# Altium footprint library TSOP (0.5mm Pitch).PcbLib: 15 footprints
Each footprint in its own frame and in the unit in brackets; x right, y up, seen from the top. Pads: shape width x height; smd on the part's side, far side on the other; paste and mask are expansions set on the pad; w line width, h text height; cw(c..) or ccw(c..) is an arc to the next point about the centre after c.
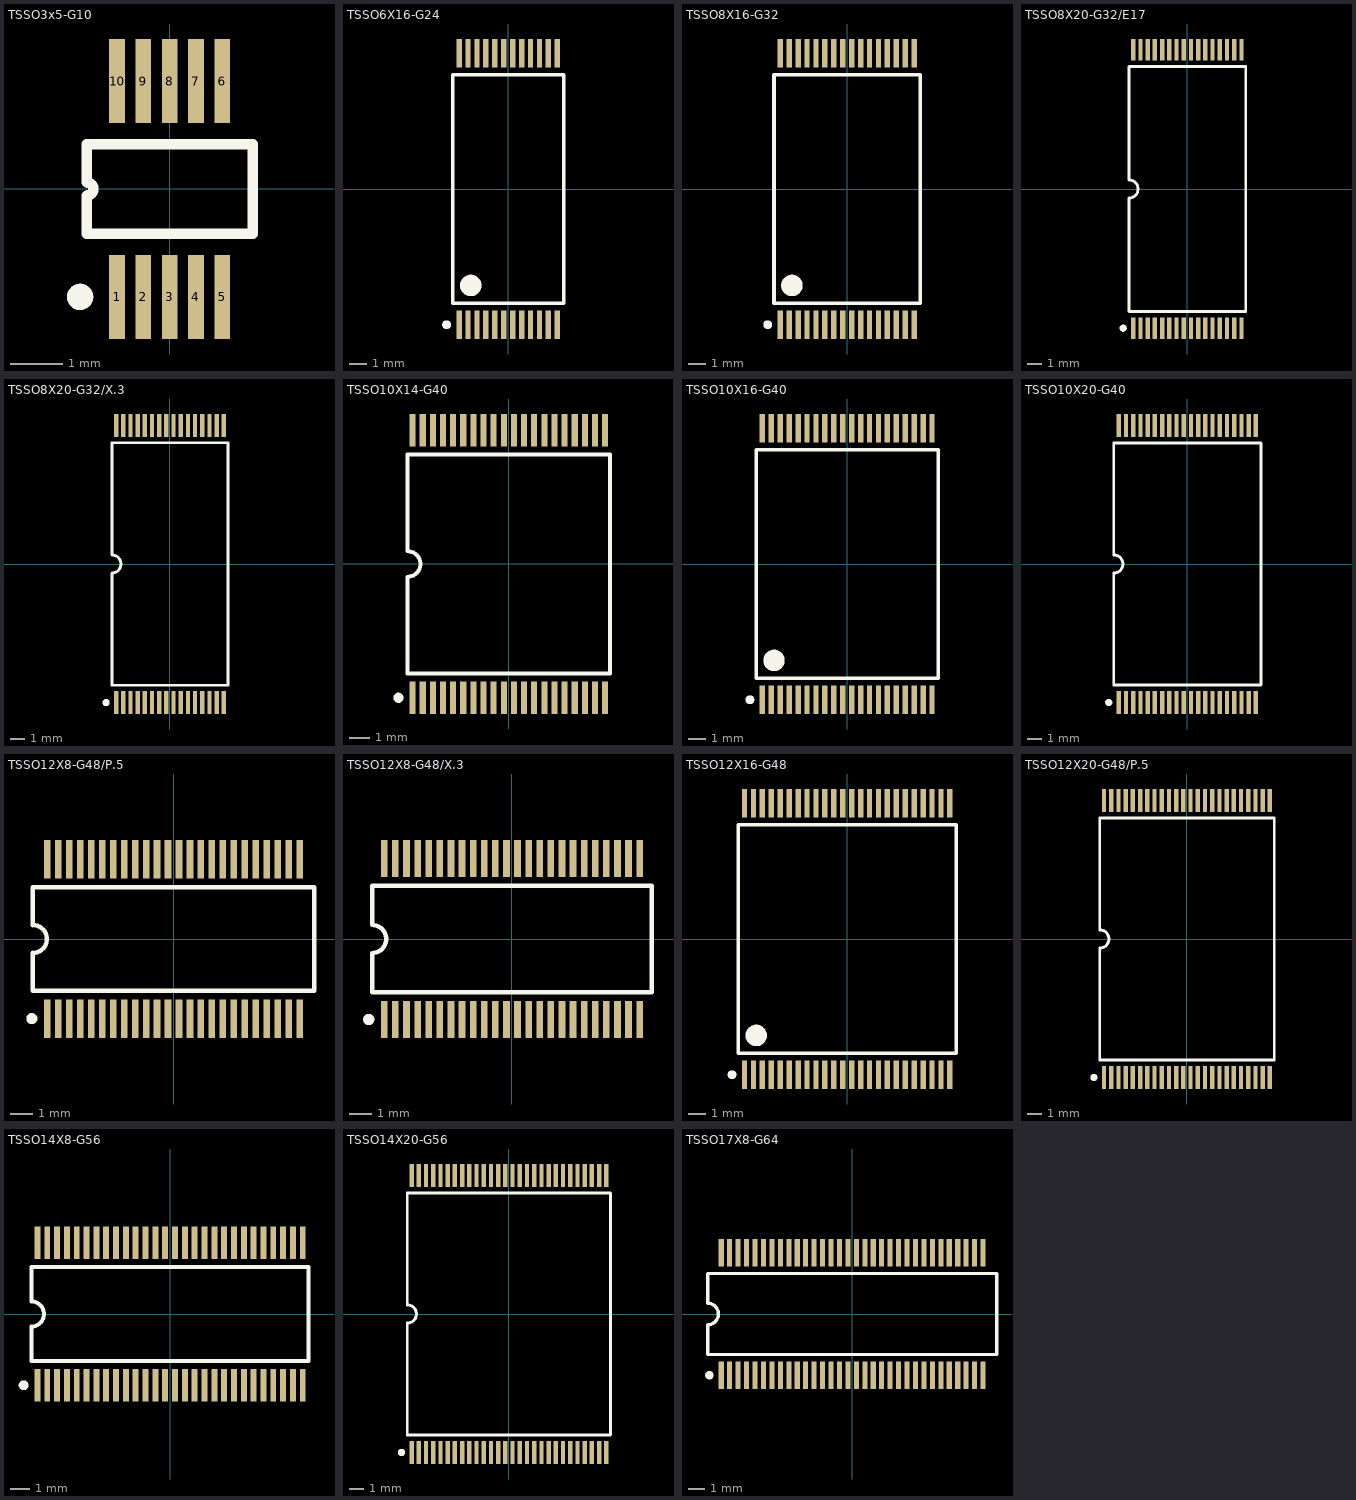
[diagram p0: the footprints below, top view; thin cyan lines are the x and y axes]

## TSSO3x5-G10 [mm]
pads (10):
  rect 0.3x1.6 smd: 1(-1,-2.05) 2(-0.5,-2.05) 3(0,-2.05) 4(0.5,-2.05) 5(1,-2.05) 6(1,2.05) 7(0.5,2.05) 8(0,2.05) 9(-0.5,2.05) 10(-1,2.05)
Top Overlay:
  circle w0.25: c-1.7,-2.05 r0.125
  lines w0.2: -1.575,-0.85 1.575,-0.85 1.575,0.85 -1.575,0.85 -1.575,0.125 cw(c-1.575,0) -1.575,-0.125 -1.575,-0.85

## TSSO6X16-G24 [mm]
pads (24):
  rect 0.3x1.6 smd: 1(-2.75,-7.6) 2(-2.25,-7.6) 3(-1.75,-7.6) 4(-1.25,-7.6) 5(-0.75,-7.6) 6(-0.25,-7.6) 7(0.25,-7.6) 8(0.75,-7.6) 9(1.25,-7.6) 10(1.75,-7.6) 11(2.25,-7.6) 12(2.75,-7.6) 13(2.75,7.6) 14(2.25,7.6) 15(1.75,7.6) 16(1.25,7.6) 17(0.75,7.6) 18(0.25,7.6) 19(-0.25,7.6) 20(-0.75,7.6) 21(-1.25,7.6) 22(-1.75,7.6) 23(-2.25,7.6) 24(-2.75,7.6)
Top Overlay:
  circle w0.6: c-2.1,-5.4 r0.3
  circle w0.25: c-3.45,-7.6 r0.125
  lines w0.2: -3.1,-6.4 3.1,-6.4 3.1,6.4 -3.1,6.4 -3.1,-0.635 -3.1,-6.4

## TSSO8X16-G32 [mm]
pads (32):
  rect 0.3x1.6 smd: 1(-3.75,-7.6) 2(-3.25,-7.6) 3(-2.75,-7.6) 4(-2.25,-7.6) 5(-1.75,-7.6) 6(-1.25,-7.6) 7(-0.75,-7.6) 8(-0.25,-7.6) 9(0.25,-7.6) 10(0.75,-7.6) 11(1.25,-7.6) 12(1.75,-7.6) 13(2.25,-7.6) 14(2.75,-7.6) 15(3.25,-7.6) 16(3.75,-7.6) 17(3.75,7.6) 18(3.25,7.6) 19(2.75,7.6) 20(2.25,7.6) 21(1.75,7.6) 22(1.25,7.6) 23(0.75,7.6) 24(0.25,7.6) 25(-0.25,7.6) 26(-0.75,7.6) 27(-1.25,7.6) 28(-1.75,7.6) 29(-2.25,7.6) 30(-2.75,7.6) 31(-3.25,7.6) 32(-3.75,7.6)
Top Overlay:
  circle w0.6: c-3.1,-5.4 r0.3
  circle w0.25: c-4.45,-7.6 r0.125
  lines w0.2: -4.1,-6.4 4.1,-6.4 4.1,6.4 -4.1,6.4 -4.1,-0.635 -4.1,-6.4

## TSSO8X20-G32/E17 [mm]
pads (32):
  rect 0.3x1.5 smd: 1(-3.75,-9.65) 2(-3.25,-9.65) 3(-2.75,-9.65) 4(-2.25,-9.65) 5(-1.75,-9.65) 6(-1.25,-9.65) 7(-0.75,-9.65) 8(-0.25,-9.65) 9(0.25,-9.65) 10(0.75,-9.65) 11(1.25,-9.65) 12(1.75,-9.65) 13(2.25,-9.65) 14(2.75,-9.65) 15(3.25,-9.65) 16(3.75,-9.65) 17(3.75,9.65) 18(3.25,9.65) 19(2.75,9.65) 20(2.25,9.65) 21(1.75,9.65) 22(1.25,9.65) 23(0.75,9.65) 24(0.25,9.65) 25(-0.25,9.65) 26(-0.75,9.65) 27(-1.25,9.65) 28(-1.75,9.65) 29(-2.25,9.65) 30(-2.75,9.65) 31(-3.25,9.65) 32(-3.75,9.65)
Top Overlay:
  circle w0.25: c-4.45,-9.65 r0.125
  lines w0.2: -4.05,-8.5 4.05,-8.5 4.05,8.5 -4.05,8.5 -4.05,0.635 cw(c-4.05,0) -4.05,-0.635 -4.05,-8.5

## TSSO8X20-G32/X.3 [mm]
pads (32):
  rect 0.3x1.6 smd: 1(-3.75,-9.65) 2(-3.25,-9.65) 3(-2.75,-9.65) 4(-2.25,-9.65) 5(-1.75,-9.65) 6(-1.25,-9.65) 7(-0.75,-9.65) 8(-0.25,-9.65) 9(0.25,-9.65) 10(0.75,-9.65) 11(1.25,-9.65) 12(1.75,-9.65) 13(2.25,-9.65) 14(2.75,-9.65) 15(3.25,-9.65) 16(3.75,-9.65) 17(3.75,9.65) 18(3.25,9.65) 19(2.75,9.65) 20(2.25,9.65) 21(1.75,9.65) 22(1.25,9.65) 23(0.75,9.65) 24(0.25,9.65) 25(-0.25,9.65) 26(-0.75,9.65) 27(-1.25,9.65) 28(-1.75,9.65) 29(-2.25,9.65) 30(-2.75,9.65) 31(-3.25,9.65) 32(-3.75,9.65)
Top Overlay:
  circle w0.25: c-4.45,-9.65 r0.125
  lines w0.2: -4.05,-8.45 -4.05,-0.635 ccw(c-4.05,0) -4.05,0.635 -4.05,8.45 4.05,8.45 4.05,-8.45 -4.05,-8.45

## TSSO10X14-G40 [mm]
pads (40):
  rect 0.3x1.6 smd: 1(-4.75,-6.6) 2(-4.25,-6.6) 3(-3.75,-6.6) 4(-3.25,-6.6) 5(-2.75,-6.6) 6(-2.25,-6.6) 7(-1.75,-6.6) 8(-1.25,-6.6) 9(-0.75,-6.6) 10(-0.25,-6.6) 11(0.25,-6.6) 12(0.75,-6.6) 13(1.25,-6.6) 14(1.75,-6.6) 15(2.25,-6.6) 16(2.75,-6.6) 17(3.25,-6.6) 18(3.75,-6.6) 19(4.25,-6.6) 20(4.75,-6.6) 21(4.75,6.6) 22(4.25,6.6) 23(3.75,6.6) 24(3.25,6.6) 25(2.75,6.6) 26(2.25,6.6) 27(1.75,6.6) 28(1.25,6.6) 29(0.75,6.6) 30(0.25,6.6) 31(-0.25,6.6) 32(-0.75,6.6) 33(-1.25,6.6) 34(-1.75,6.6) 35(-2.25,6.6) 36(-2.75,6.6) 37(-3.25,6.6) 38(-3.75,6.6) 39(-4.25,6.6) 40(-4.75,6.6)
Top Overlay:
  circle w0.25: c-5.45,-6.6 r0.125
  lines w0.2: -5,-5.4 5,-5.4 5,5.4 -5,5.4 -5,0.635 cw(c-5,0) -5,-0.635 -5,-5.4

## TSSO10X16-G40 [mm]
pads (40):
  rect 0.3x1.6 smd: 1(-4.75,-7.6) 2(-4.25,-7.6) 3(-3.75,-7.6) 4(-3.25,-7.6) 5(-2.75,-7.6) 6(-2.25,-7.6) 7(-1.75,-7.6) 8(-1.25,-7.6) 9(-0.75,-7.6) 10(-0.25,-7.6) 11(0.25,-7.6) 12(0.75,-7.6) 13(1.25,-7.6) 14(1.75,-7.6) 15(2.25,-7.6) 16(2.75,-7.6) 17(3.25,-7.6) 18(3.75,-7.6) 19(4.25,-7.6) 20(4.75,-7.6) 21(4.75,7.6) 22(4.25,7.6) 23(3.75,7.6) 24(3.25,7.6) 25(2.75,7.6) 26(2.25,7.6) 27(1.75,7.6) 28(1.25,7.6) 29(0.75,7.6) 30(0.25,7.6) 31(-0.25,7.6) 32(-0.75,7.6) 33(-1.25,7.6) 34(-1.75,7.6) 35(-2.25,7.6) 36(-2.75,7.6) 37(-3.25,7.6) 38(-3.75,7.6) 39(-4.25,7.6) 40(-4.75,7.6)
Top Overlay:
  circle w0.6: c-4.1,-5.4 r0.3
  circle w0.25: c-5.45,-7.6 r0.125
  lines w0.2: -5.1,-6.4 5.1,-6.4 5.1,6.4 -5.1,6.4 -5.1,-0.635 -5.1,-6.4

## TSSO10X20-G40 [mm]
pads (40):
  rect 0.3x1.6 smd: 1(-4.75,-9.6) 2(-4.25,-9.6) 3(-3.75,-9.6) 4(-3.25,-9.6) 5(-2.75,-9.6) 6(-2.25,-9.6) 7(-1.75,-9.6) 8(-1.25,-9.6) 9(-0.75,-9.6) 10(-0.25,-9.6) 11(0.25,-9.6) 12(0.75,-9.6) 13(1.25,-9.6) 14(1.75,-9.6) 15(2.25,-9.6) 16(2.75,-9.6) 17(3.25,-9.6) 18(3.75,-9.6) 19(4.25,-9.6) 20(4.75,-9.6) 21(4.75,9.6) 22(4.25,9.6) 23(3.75,9.6) 24(3.25,9.6) 25(2.75,9.6) 26(2.25,9.6) 27(1.75,9.6) 28(1.25,9.6) 29(0.75,9.6) 30(0.25,9.6) 31(-0.25,9.6) 32(-0.75,9.6) 33(-1.25,9.6) 34(-1.75,9.6) 35(-2.25,9.6) 36(-2.75,9.6) 37(-3.25,9.6) 38(-3.75,9.6) 39(-4.25,9.6) 40(-4.75,9.6)
Top Overlay:
  circle w0.25: c-5.45,-9.6 r0.125
  lines w0.2: -5.1,-8.4 -5.1,-0.635 ccw(c-5.1,0) -5.1,0.635 -5.1,8.4 5.1,8.4 5.1,-8.4 -5.1,-8.4

## TSSO12X8-G48/P.5 [mm]
pads (48):
  rect 0.3x1.75 smd: 1(-5.75,-3.625) 2(-5.25,-3.625) 3(-4.75,-3.625) 4(-4.25,-3.625) 5(-3.75,-3.625) 6(-3.25,-3.625) 7(-2.75,-3.625) 8(-2.25,-3.625) 9(-1.75,-3.625) 10(-1.25,-3.625) 11(-0.75,-3.625) 12(-0.25,-3.625) 13(0.25,-3.625) 14(0.75,-3.625) 15(1.25,-3.625) 16(1.75,-3.625) 17(2.25,-3.625) 18(2.75,-3.625) 19(3.25,-3.625) 20(3.75,-3.625) 21(4.25,-3.625) 22(4.75,-3.625) 23(5.25,-3.625) 24(5.75,-3.625) 25(5.75,3.625) 26(5.25,3.625) 27(4.75,3.625) 28(4.25,3.625) 29(3.75,3.625) 30(3.25,3.625) 31(2.75,3.625) 32(2.25,3.625) 33(1.75,3.625) 34(1.25,3.625) 35(0.75,3.625) 36(0.25,3.625) 37(-0.25,3.625) 38(-0.75,3.625) 39(-1.25,3.625) 40(-1.75,3.625) 41(-2.25,3.625) 42(-2.75,3.625) 43(-3.25,3.625) 44(-3.75,3.625) 45(-4.25,3.625) 46(-4.75,3.625) 47(-5.25,3.625) 48(-5.75,3.625)
Top Overlay:
  circle w0.25: c-6.45,-3.625 r0.125
  lines w0.2: -6.4,-2.35 6.4,-2.35 6.4,2.35 -6.4,2.35 -6.4,0.635 cw(c-6.4,0) -6.4,-0.635 -6.4,-2.35

## TSSO12X8-G48/X.3 [mm]
pads (48):
  rect 0.3x1.65 smd: 1(-5.75,-3.625) 2(-5.25,-3.625) 3(-4.75,-3.625) 4(-4.25,-3.625) 5(-3.75,-3.625) 6(-3.25,-3.625) 7(-2.75,-3.625) 8(-2.25,-3.625) 9(-1.75,-3.625) 10(-1.25,-3.625) 11(-0.75,-3.625) 12(-0.25,-3.625) 13(0.25,-3.625) 14(0.75,-3.625) 15(1.25,-3.625) 16(1.75,-3.625) 17(2.25,-3.625) 18(2.75,-3.625) 19(3.25,-3.625) 20(3.75,-3.625) 21(4.25,-3.625) 22(4.75,-3.625) 23(5.25,-3.625) 24(5.75,-3.625) 25(5.75,3.625) 26(5.25,3.625) 27(4.75,3.625) 28(4.25,3.625) 29(3.75,3.625) 30(3.25,3.625) 31(2.75,3.625) 32(2.25,3.625) 33(1.75,3.625) 34(1.25,3.625) 35(0.75,3.625) 36(0.25,3.625) 37(-0.25,3.625) 38(-0.75,3.625) 39(-1.25,3.625) 40(-1.75,3.625) 41(-2.25,3.625) 42(-2.75,3.625) 43(-3.25,3.625) 44(-3.75,3.625) 45(-4.25,3.625) 46(-4.75,3.625) 47(-5.25,3.625) 48(-5.75,3.625)
Top Overlay:
  circle w0.25: c-6.45,-3.625 r0.125
  lines w0.2: -6.3,-2.4 6.3,-2.4 6.3,2.4 -6.3,2.4 -6.3,0.635 cw(c-6.3,0) -6.3,-0.635 -6.3,-2.4

## TSSO12X16-G48 [mm]
pads (48):
  rect 0.3x1.6 smd: 1(-5.75,-7.6) 2(-5.25,-7.6) 3(-4.75,-7.6) 4(-4.25,-7.6) 5(-3.75,-7.6) 6(-3.25,-7.6) 7(-2.75,-7.6) 8(-2.25,-7.6) 9(-1.75,-7.6) 10(-1.25,-7.6) 11(-0.75,-7.6) 12(-0.25,-7.6) 13(0.25,-7.6) 14(0.75,-7.6) 15(1.25,-7.6) 16(1.75,-7.6) 17(2.25,-7.6) 18(2.75,-7.6) 19(3.25,-7.6) 20(3.75,-7.6) 21(4.25,-7.6) 22(4.75,-7.6) 23(5.25,-7.6) 24(5.75,-7.6) 25(5.75,7.6) 26(5.25,7.6) 27(4.75,7.6) 28(4.25,7.6) 29(3.75,7.6) 30(3.25,7.6) 31(2.75,7.6) 32(2.25,7.6) 33(1.75,7.6) 34(1.25,7.6) 35(0.75,7.6) 36(0.25,7.6) 37(-0.25,7.6) 38(-0.75,7.6) 39(-1.25,7.6) 40(-1.75,7.6) 41(-2.25,7.6) 42(-2.75,7.6) 43(-3.25,7.6) 44(-3.75,7.6) 45(-4.25,7.6) 46(-4.75,7.6) 47(-5.25,7.6) 48(-5.75,7.6)
Top Overlay:
  circle w0.6: c-5.1,-5.4 r0.3
  circle w0.25: c-6.45,-7.6 r0.125
  lines w0.2: -6.1,-6.4 6.1,-6.4 6.1,6.4 -6.1,6.4 -6.1,-0.635 -6.1,-6.4

## TSSO12X20-G48/P.5 [mm]
pads (48):
  rect 0.3x1.6 smd: 1(-5.75,-9.6) 2(-5.25,-9.6) 3(-4.75,-9.6) 4(-4.25,-9.6) 5(-3.75,-9.6) 6(-3.25,-9.6) 7(-2.75,-9.6) 8(-2.25,-9.6) 9(-1.75,-9.6) 10(-1.25,-9.6) 11(-0.75,-9.6) 12(-0.25,-9.6) 13(0.25,-9.6) 14(0.75,-9.6) 15(1.25,-9.6) 16(1.75,-9.6) 17(2.25,-9.6) 18(2.75,-9.6) 19(3.25,-9.6) 20(3.75,-9.6) 21(4.25,-9.6) 22(4.75,-9.6) 23(5.25,-9.6) 24(5.75,-9.6) 25(5.75,9.6) 26(5.25,9.6) 27(4.75,9.6) 28(4.25,9.6) 29(3.75,9.6) 30(3.25,9.6) 31(2.75,9.6) 32(2.25,9.6) 33(1.75,9.6) 34(1.25,9.6) 35(0.75,9.6) 36(0.25,9.6) 37(-0.25,9.6) 38(-0.75,9.6) 39(-1.25,9.6) 40(-1.75,9.6) 41(-2.25,9.6) 42(-2.75,9.6) 43(-3.25,9.6) 44(-3.75,9.6) 45(-4.25,9.6) 46(-4.75,9.6) 47(-5.25,9.6) 48(-5.75,9.6)
Top Overlay:
  circle w0.25: c-6.45,-9.6 r0.125
  lines w0.2: -6.05,-8.4 -6.05,-0.635 ccw(c-6.05,0) -6.05,0.635 -6.05,8.4 6.05,8.4 6.05,-8.4 -6.05,-8.4

## TSSO14X8-G56 [mm]
pads (56):
  rect 0.3x1.65 smd: 1(-6.75,-3.625) 2(-6.25,-3.625) 3(-5.75,-3.625) 4(-5.25,-3.625) 5(-4.75,-3.625) 6(-4.25,-3.625) 7(-3.75,-3.625) 8(-3.25,-3.625) 9(-2.75,-3.625) 10(-2.25,-3.625) 11(-1.75,-3.625) 12(-1.25,-3.625) 13(-0.75,-3.625) 14(-0.25,-3.625) 15(0.25,-3.625) 16(0.75,-3.625) 17(1.25,-3.625) 18(1.75,-3.625) 19(2.25,-3.625) 20(2.75,-3.625) 21(3.25,-3.625) 22(3.75,-3.625) 23(4.25,-3.625) 24(4.75,-3.625) 25(5.25,-3.625) 26(5.75,-3.625) 27(6.25,-3.625) 28(6.75,-3.625) 29(6.75,3.625) 30(6.25,3.625) 31(5.75,3.625) 32(5.25,3.625) 33(4.75,3.625) 34(4.25,3.625) 35(3.75,3.625) 36(3.25,3.625) 37(2.75,3.625) 38(2.25,3.625) 39(1.75,3.625) 40(1.25,3.625) 41(0.75,3.625) 42(0.25,3.625) 43(-0.25,3.625) 44(-0.75,3.625) 45(-1.25,3.625) 46(-1.75,3.625) 47(-2.25,3.625) 48(-2.75,3.625) 49(-3.25,3.625) 50(-3.75,3.625) 51(-4.25,3.625) 52(-4.75,3.625) 53(-5.25,3.625) 54(-5.75,3.625) 55(-6.25,3.625) 56(-6.75,3.625)
Top Overlay:
  circle w0.25: c-7.45,-3.625 r0.125
  lines w0.2: -7.05,-2.4 -7.05,-0.635 ccw(c-7.05,0) -7.05,0.635 -7.05,2.4 7.05,2.4 7.05,-2.4 -7.05,-2.4

## TSSO14X20-G56 [mm]
pads (56):
  rect 0.3x1.6 smd: 1(-6.75,-9.6) 2(-6.25,-9.6) 3(-5.75,-9.6) 4(-5.25,-9.6) 5(-4.75,-9.6) 6(-4.25,-9.6) 7(-3.75,-9.6) 8(-3.25,-9.6) 9(-2.75,-9.6) 10(-2.25,-9.6) 11(-1.75,-9.6) 12(-1.25,-9.6) 13(-0.75,-9.6) 14(-0.25,-9.6) 15(0.25,-9.6) 16(0.75,-9.6) 17(1.25,-9.6) 18(1.75,-9.6) 19(2.25,-9.6) 20(2.75,-9.6) 21(3.25,-9.6) 22(3.75,-9.6) 23(4.25,-9.6) 24(4.75,-9.6) 25(5.25,-9.6) 26(5.75,-9.6) 27(6.25,-9.6) 28(6.75,-9.6) 29(6.75,9.6) 30(6.25,9.6) 31(5.75,9.6) 32(5.25,9.6) 33(4.75,9.6) 34(4.25,9.6) 35(3.75,9.6) 36(3.25,9.6) 37(2.75,9.6) 38(2.25,9.6) 39(1.75,9.6) 40(1.25,9.6) 41(0.75,9.6) 42(0.25,9.6) 43(-0.25,9.6) 44(-0.75,9.6) 45(-1.25,9.6) 46(-1.75,9.6) 47(-2.25,9.6) 48(-2.75,9.6) 49(-3.25,9.6) 50(-3.75,9.6) 51(-4.25,9.6) 52(-4.75,9.6) 53(-5.25,9.6) 54(-5.75,9.6) 55(-6.25,9.6) 56(-6.75,9.6)
Top Overlay:
  circle w0.25: c-7.45,-9.6 r0.125
  lines w0.2: -7.05,-8.4 7.05,-8.4 7.05,8.4 -7.05,8.4 -7.05,0.635 cw(c-7.05,0) -7.05,-0.635 -7.05,-8.4

## TSSO17X8-G64 [mm]
pads (64):
  rect 0.3x1.65 smd: 1(-7.75,-3.625) 2(-7.25,-3.625) 3(-6.75,-3.625) 4(-6.25,-3.625) 5(-5.75,-3.625) 6(-5.25,-3.625) 7(-4.75,-3.625) 8(-4.25,-3.625) 9(-3.75,-3.625) 10(-3.25,-3.625) 11(-2.75,-3.625) 12(-2.25,-3.625) 13(-1.75,-3.625) 14(-1.25,-3.625) 15(-0.75,-3.625) 16(-0.25,-3.625) 17(0.25,-3.625) 18(0.75,-3.625) 19(1.25,-3.625) 20(1.75,-3.625) 21(2.25,-3.625) 22(2.75,-3.625) 23(3.25,-3.625) 24(3.75,-3.625) 25(4.25,-3.625) 26(4.75,-3.625) 27(5.25,-3.625) 28(5.75,-3.625) 29(6.25,-3.625) 30(6.75,-3.625) 31(7.25,-3.625) 32(7.75,-3.625) 33(7.75,3.625) 34(7.25,3.625) 35(6.75,3.625) 36(6.25,3.625) 37(5.75,3.625) 38(5.25,3.625) 39(4.75,3.625) 40(4.25,3.625) 41(3.75,3.625) 42(3.25,3.625) 43(2.75,3.625) 44(2.25,3.625) 45(1.75,3.625) 46(1.25,3.625) 47(0.75,3.625) 48(0.25,3.625) 49(-0.25,3.625) 50(-0.75,3.625) 51(-1.25,3.625) 52(-1.75,3.625) 53(-2.25,3.625) 54(-2.75,3.625) 55(-3.25,3.625) 56(-3.75,3.625) 57(-4.25,3.625) 58(-4.75,3.625) 59(-5.25,3.625) 60(-5.75,3.625) 61(-6.25,3.625) 62(-6.75,3.625) 63(-7.25,3.625) 64(-7.75,3.625)
Top Overlay:
  circle w0.25: c-8.45,-3.625 r0.125
  lines w0.2: -8.55,-2.4 8.55,-2.4 8.55,2.4 -8.55,2.4 -8.55,0.635 cw(c-8.55,0) -8.55,-0.635 -8.55,-2.4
